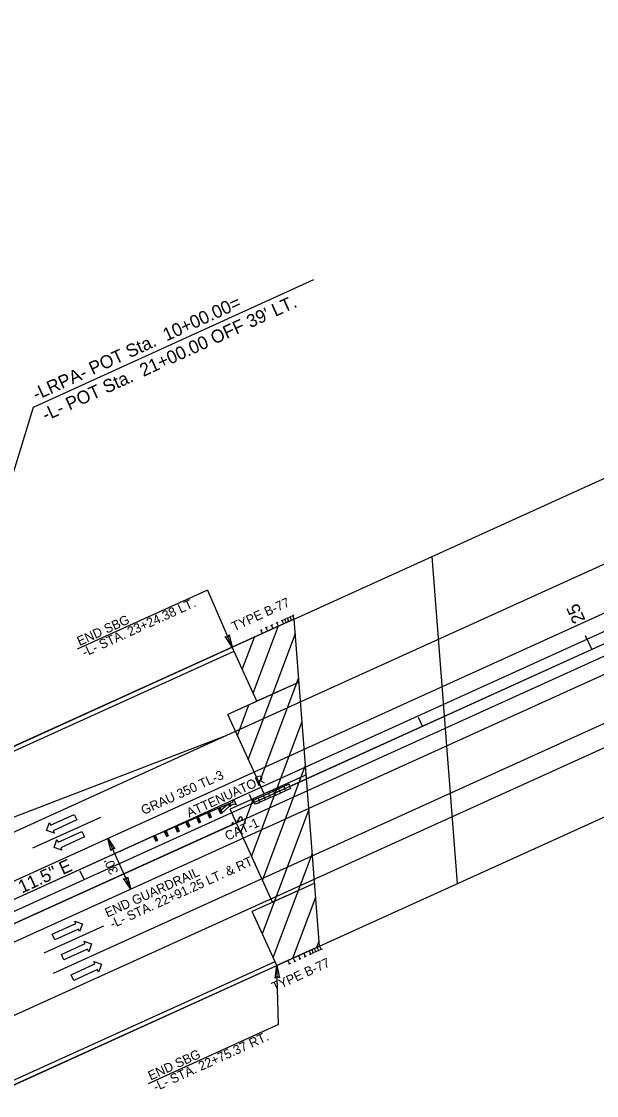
# Model space of a CAD drawing. Extents: x 2242984 to 2250974, y 661492 to 664681.
# Drawn here: x 2248742 to 2249051, y 663168 to 663746 of the extents above; entities that cross this region are included whole.
import ezdxf

# ---------------------------------------------------------------- set-up
doc = ezdxf.new("R2010")
doc.units = 0
for name, color, linetype in [('Prop Approach Slab', 7, 'Continuous'), ('Prop Approach Slab Hatching', 7, 'Continuous'), ('Prop Conc Barrier Precast Reinforced Single Face', 7, 'Continuous'), ('Prop Conc Shoulder Berm Gutter', 7, 'Continuous'), ('Prop Dimension', 7, 'Continuous'), ('Prop Dimension Text', 7, 'Continuous'), ('Prop DSN Text', 7, 'Continuous'), ('Prop EOT', 7, 'Continuous'), ('Prop Guardrail', 7, 'Continuous'), ('Prop Guardrail Anchor Unit CELL', 7, 'Continuous'), ('Prop Guardrail Attenuator CELL', 7, 'Continuous'), ('Prop Horizontal Alignment', 7, 'Continuous'), ('Prop Horizontal Alignment Direction Label', 7, 'Continuous'), ('Prop Horizontal Alignment Station Label', 7, 'Continuous'), ('Prop Horizontal Alignment Tick Label', 7, 'Continuous'), ('Prop Horizontal Alignment Tick Large', 7, 'Continuous'), ('Prop Horizontal Alignment Tick Small', 7, 'Continuous'), ('Prop Lane Arrow CELL', 7, 'Continuous'), ('Prop Lane Lines', 7, 'Continuous'), ('Prop Paved Shoulder', 7, 'Continuous'), ('Prop Roadway Bridge', 7, 'Continuous'), ('Prop Structure Anchor Unit CELL', 7, 'Continuous'), ('Prop Terminator CELL', 7, 'Continuous'), ('Scratch_Level_6', 7, 'Continuous'), ('Scratch_Level_8', 7, 'Continuous')]:
    doc.layers.add(name, color=color, linetype=linetype)

msp = doc.modelspace()

# ---------------------------------------------------------------- linework, layer by layer
at = {"layer": 'Prop Approach Slab'}
for p, q in [((2248888.56, 663424.38), (2248855.2, 663409.22)), ((2248868.43, 663380.09), (2248855.2, 663409.22)), ((2248891.19, 663390.43), (2248852.86, 663373.01)), ((2248891.19, 663390.43), (2248868.43, 663380.09)), ((2248875.62, 663383.35), (2248852.86, 663373.01)), ((2248872.3, 663330.22), (2248852.86, 663373.01)), ((2248895.06, 663340.56), (2248854.07, 663321.94)), ((2248895.06, 663340.56), (2248872.3, 663330.22)), ((2248876.82, 663271.87), (2248854.07, 663321.94)), ((2248899.58, 663282.21), (2248865.99, 663266.95)), ((2248899.58, 663282.21), (2248876.82, 663271.87)), ((2248879.23, 663237.81), (2248865.99, 663266.95)), ((2248902.21, 663248.25), (2248879.23, 663237.81))]:
    msp.add_line(p, q, dxfattribs=at)
at = {"layer": 'Prop Approach Slab Hatching'}
for p, q in [((2248866.47, 663384.41), (2248879.95, 663420.47)), ((2248860.61, 663397.31), (2248867.09, 663414.62)), ((2248863.84, 663348.84), (2248889.17, 663416.57)), ((2248869.7, 663335.95), (2248891, 663392.92)), ((2248857.98, 663361.73), (2248864.12, 663378.13)), ((2248865.62, 663296.51), (2248892.83, 663369.27)), ((2248871.48, 663283.61), (2248894.67, 663345.62)), ((2248859.77, 663309.4), (2248866.59, 663327.63)), ((2248871.44, 663254.95), (2248896.5, 663321.97)), ((2248877.3, 663242.06), (2248898.33, 663298.32)), ((2248887.85, 663241.73), (2248900.16, 663274.67)), ((2248900.71, 663247.57), (2248902, 663251.01))]:
    msp.add_line(p, q, dxfattribs=at)
at = {"layer": 'Prop Conc Barrier Precast Reinforced Single Face'}
msp.add_line((2248886.12, 663334.3), (2249152.79, 663455.44), dxfattribs=at)
at = {"layer": 'Prop Conc Shoulder Berm Gutter'}
for p, q in [((2248644.9, 663311.13), (2248856.16, 663407.1)), ((2248645.24, 663134.09), (2248878.26, 663239.94))]:
    msp.add_line(p, q, dxfattribs=at)
at = {"layer": 'Prop Dimension'}
msp.add_line((2248800.6, 663278.98), (2248788.19, 663306.3), dxfattribs=at)
at = {"layer": 'Prop DSN Text'}
for p, q in [((2248841.8, 663440.05), (2248771.74, 663408.13)), ((2248841.8, 663440.05), (2248855.2, 663409.22)), ((2248880.01, 663206), (2248879.23, 663237.81)), ((2248880.01, 663206), (2248809.95, 663174.07))]:
    msp.add_line(p, q, dxfattribs=at)
at = {"layer": 'Prop EOT'}
for p, q in [((2248850.37, 663360.9), (2249423.96, 663621.46)), ((2248200.21, 663039.2), (2249433.89, 663599.6)), ((2248212.61, 663011.89), (2249446.3, 663572.29)), ((2248401.88, 663058.32), (2249188.04, 663415.44)), ((2248850.37, 663360.9), (2248663.29, 663289.12))]:
    msp.add_line(p, q, dxfattribs=at)
at = {"layer": 'Prop Guardrail'}
for p, q in [((2248871.49, 663416.62), (2248643.94, 663313.26)), ((2248855.32, 663313.72), (2247994.71, 662922.79)), ((2248855.32, 663313.72), (2247994.71, 662922.79)), ((2247989.75, 662933.71), (2248810.53, 663306.55)), ((2247989.75, 662933.71), (2248810.53, 663306.55)), ((2248646.2, 663131.96), (2248885.14, 663240.5))]:
    msp.add_line(p, q, dxfattribs=at)
at = {"layer": 'Prop Guardrail Anchor Unit CELL'}
for p, q in [((2248855.39, 663325.82), (2248856.11, 663327.09)), ((2248855.39, 663325.82), (2248856.11, 663327.09)), ((2248856.11, 663327.09), (2248857.32, 663324.41)), ((2248856.11, 663327.09), (2248857.32, 663324.41)), ((2248810.53, 663306.55), (2248853.47, 663325.04)), ((2248810.53, 663306.55), (2248853.47, 663325.04)), ((2248847.59, 663322.5), (2248848.8, 663319.69)), ((2248847.59, 663322.5), (2248849.11, 663321.49)), ((2248847.59, 663322.5), (2248848.8, 663319.69)), ((2248847.59, 663322.5), (2248849.11, 663321.49)), ((2248848.2, 663321.1), (2248848.51, 663322.9)), ((2248848.2, 663321.1), (2248848.51, 663322.9)), ((2248848.2, 663321.1), (2248849.11, 663321.49)), ((2248848.2, 663321.1), (2248849.11, 663321.49)), ((2248849.72, 663320.09), (2248848.2, 663321.1)), ((2248849.72, 663320.09), (2248848.2, 663321.1)), ((2248848.51, 663322.9), (2248849.72, 663320.09)), ((2248848.51, 663322.9), (2248849.72, 663320.09)), ((2248849.11, 663321.49), (2248848.8, 663319.69)), ((2248849.11, 663321.49), (2248848.8, 663319.69)), ((2248849.11, 663321.49), (2248853.01, 663324.84)), ((2248849.11, 663321.49), (2248853.01, 663324.84)), ((2248849.72, 663320.09), (2248853.6, 663323.46)), ((2248849.72, 663320.09), (2248853.6, 663323.46)), ((2248853.01, 663324.84), (2248853.6, 663323.46)), ((2248854.52, 663323.85), (2248853.01, 663324.84)), ((2248853.01, 663324.84), (2248853.6, 663323.46)), ((2248854.52, 663323.85), (2248853.01, 663324.84)), ((2248853.53, 663324.98), (2248855.39, 663325.82)), ((2248853.53, 663324.98), (2248855.39, 663325.82)), ((2248853.78, 663324.42), (2248853.53, 663324.98)), ((2248853.78, 663324.42), (2248853.53, 663324.98)), ((2248853.93, 663325.23), (2248853.6, 663323.46)), ((2248853.93, 663325.23), (2248853.6, 663323.46)), ((2248853.6, 663323.46), (2248854.52, 663323.85)), ((2248853.6, 663323.46), (2248854.52, 663323.85)), ((2248853.6, 663323.46), (2248854.06, 663323.66)), ((2248853.6, 663323.46), (2248854.06, 663323.66)), ((2248854.03, 663323.86), (2248853.78, 663324.42)), ((2248854.03, 663323.86), (2248853.78, 663324.42)), ((2248853.93, 663325.23), (2248854.52, 663323.85)), ((2248853.93, 663325.23), (2248854.52, 663323.85)), ((2248855.9, 663324.71), (2248854.03, 663323.86)), ((2248855.9, 663324.71), (2248854.03, 663323.86)), ((2248857.32, 663324.41), (2248855.9, 663324.71)), ((2248857.32, 663324.41), (2248855.9, 663324.71)), ((2248830.23, 663315.03), (2248831.14, 663315.43)), ((2248830.23, 663315.03), (2248831.14, 663315.43)), ((2248830.23, 663315.03), (2248831.43, 663312.24)), ((2248830.23, 663315.03), (2248831.74, 663314.03)), ((2248830.23, 663315.03), (2248831.43, 663312.24)), ((2248830.23, 663315.03), (2248831.74, 663314.03)), ((2248830.83, 663313.64), (2248831.14, 663315.43)), ((2248830.83, 663313.64), (2248831.14, 663315.43)), ((2248831.14, 663315.43), (2248832.34, 663312.64)), ((2248831.14, 663315.43), (2248832.34, 663312.64)), ((2248836.01, 663317.52), (2248837.25, 663314.64)), ((2248836.01, 663317.52), (2248837.55, 663316.48)), ((2248836.01, 663317.52), (2248837.25, 663314.64)), ((2248836.01, 663317.52), (2248837.55, 663316.48)), ((2248836.63, 663316.08), (2248836.93, 663317.92)), ((2248836.63, 663316.08), (2248836.93, 663317.92)), ((2248836.63, 663316.08), (2248837.55, 663316.48)), ((2248836.63, 663316.08), (2248837.55, 663316.48)), ((2248838.17, 663315.04), (2248836.63, 663316.08)), ((2248838.17, 663315.04), (2248836.63, 663316.08)), ((2248836.93, 663317.92), (2248838.17, 663315.04)), ((2248836.93, 663317.92), (2248838.17, 663315.04)), ((2248837.55, 663316.48), (2248837.25, 663314.64)), ((2248837.55, 663316.48), (2248837.25, 663314.64)), ((2248837.25, 663314.64), (2248838.17, 663315.04)), ((2248837.25, 663314.64), (2248838.17, 663315.04)), ((2248841.8, 663320.01), (2248842.99, 663317.26)), ((2248841.8, 663320.01), (2248843.31, 663319.03)), ((2248841.8, 663320.01), (2248842.99, 663317.26)), ((2248841.8, 663320.01), (2248843.31, 663319.03)), ((2248842.39, 663318.64), (2248842.72, 663320.41)), ((2248842.39, 663318.64), (2248842.72, 663320.41)), ((2248842.39, 663318.64), (2248843.31, 663319.03)), ((2248842.39, 663318.64), (2248843.31, 663319.03)), ((2248843.91, 663317.65), (2248842.39, 663318.64)), ((2248843.91, 663317.65), (2248842.39, 663318.64)), ((2248842.72, 663320.41), (2248843.91, 663317.65)), ((2248842.72, 663320.41), (2248843.91, 663317.65)), ((2248843.31, 663319.03), (2248842.99, 663317.26)), ((2248843.31, 663319.03), (2248842.99, 663317.26)), ((2248842.99, 663317.26), (2248843.91, 663317.65)), ((2248842.99, 663317.26), (2248843.91, 663317.65)), ((2248848.8, 663319.69), (2248849.72, 663320.09)), ((2248848.8, 663319.69), (2248849.72, 663320.09)), ((2248855.63, 663314.75), (2248854.99, 663314.46)), ((2248855.32, 663313.72), (2248858.55, 663315.19)), ((2248855.32, 663313.72), (2248855.63, 663314.75)), ((2248855.96, 663314.01), (2248855.63, 663314.75)), ((2248858.3, 663315.52), (2248856.74, 663314.37)), ((2248858.46, 663316.03), (2248857.82, 663315.74)), ((2248857.82, 663315.74), (2248858.15, 663315.01)), ((2248858.79, 663315.3), (2248857.82, 663315.74)), ((2248858.15, 663315.01), (2248858.46, 663316.03)), ((2248858.15, 663315.01), (2248858.79, 663315.3)), ((2248858.79, 663315.3), (2248858.46, 663316.03)), ((2248858.73, 663317.01), (2248858.5, 663315.94)), ((2248858.55, 663315.19), (2248860.11, 663315.9)), ((2248858.67, 663315.24), (2248858.55, 663315.19)), ((2248818.65, 663310.05), (2248819.86, 663307.25)), ((2248818.65, 663310.05), (2248820.17, 663309.04)), ((2248818.65, 663310.05), (2248819.86, 663307.25)), ((2248818.65, 663310.05), (2248820.17, 663309.04)), ((2248819.25, 663308.65), (2248819.57, 663310.45)), ((2248819.25, 663308.65), (2248819.57, 663310.45)), ((2248819.25, 663308.65), (2248820.17, 663309.04)), ((2248819.25, 663308.65), (2248820.17, 663309.04)), ((2248819.57, 663310.45), (2248820.77, 663307.64)), ((2248819.57, 663310.45), (2248820.77, 663307.64)), ((2248820.17, 663309.04), (2248819.86, 663307.25)), ((2248820.17, 663309.04), (2248819.86, 663307.25)), ((2248824.44, 663312.54), (2248825.64, 663309.74)), ((2248824.44, 663312.54), (2248825.96, 663311.54)), ((2248824.44, 663312.54), (2248825.64, 663309.74)), ((2248824.44, 663312.54), (2248825.96, 663311.54)), ((2248825.04, 663311.14), (2248825.36, 663312.94)), ((2248825.04, 663311.14), (2248825.36, 663312.94)), ((2248825.04, 663311.14), (2248825.96, 663311.54)), ((2248825.04, 663311.14), (2248825.96, 663311.54)), ((2248826.56, 663310.14), (2248825.04, 663311.14)), ((2248826.56, 663310.14), (2248825.04, 663311.14)), ((2248825.36, 663312.94), (2248826.56, 663310.14)), ((2248825.36, 663312.94), (2248826.56, 663310.14)), ((2248825.96, 663311.54), (2248825.64, 663309.74)), ((2248825.96, 663311.54), (2248825.64, 663309.74)), ((2248825.64, 663309.74), (2248826.56, 663310.14)), ((2248825.64, 663309.74), (2248826.56, 663310.14)), ((2248830.83, 663313.64), (2248831.74, 663314.03)), ((2248830.83, 663313.64), (2248831.74, 663314.03)), ((2248832.34, 663312.64), (2248830.83, 663313.64)), ((2248832.34, 663312.64), (2248830.83, 663313.64)), ((2248831.74, 663314.03), (2248831.43, 663312.24)), ((2248831.74, 663314.03), (2248831.43, 663312.24)), ((2248831.43, 663312.24), (2248832.34, 663312.64)), ((2248831.43, 663312.24), (2248832.34, 663312.64)), ((2248854.99, 663314.46), (2248855.32, 663313.72)), ((2248855.96, 663314.01), (2248854.99, 663314.46)), ((2248855.32, 663313.72), (2248855.96, 663314.01)), ((2248812.86, 663307.56), (2248813.78, 663307.96)), ((2248812.86, 663307.56), (2248813.78, 663307.96)), ((2248812.86, 663307.56), (2248814.05, 663304.8)), ((2248814.37, 663306.58), (2248812.86, 663307.56)), ((2248812.86, 663307.56), (2248814.05, 663304.8)), ((2248814.37, 663306.58), (2248812.86, 663307.56)), ((2248813.45, 663306.18), (2248813.78, 663307.96)), ((2248813.45, 663306.18), (2248813.78, 663307.96)), ((2248813.45, 663306.18), (2248814.37, 663306.58)), ((2248813.45, 663306.18), (2248814.37, 663306.58)), ((2248814.97, 663305.2), (2248813.45, 663306.18)), ((2248814.97, 663305.2), (2248813.45, 663306.18)), ((2248813.78, 663307.96), (2248814.97, 663305.2)), ((2248813.78, 663307.96), (2248814.37, 663306.58)), ((2248813.78, 663307.96), (2248814.97, 663305.2)), ((2248813.78, 663307.96), (2248814.37, 663306.58)), ((2248814.37, 663306.58), (2248814.05, 663304.8)), ((2248814.37, 663306.58), (2248814.05, 663304.8)), ((2248814.05, 663304.8), (2248814.97, 663305.2)), ((2248814.05, 663304.8), (2248814.97, 663305.2)), ((2248820.77, 663307.64), (2248819.25, 663308.65)), ((2248820.77, 663307.64), (2248819.25, 663308.65)), ((2248819.86, 663307.25), (2248820.77, 663307.64)), ((2248819.86, 663307.25), (2248820.77, 663307.64))]:
    msp.add_line(p, q, dxfattribs=at)
msp.add_ellipse((2248859.7, 663316.8), major_axis=(-0.411, 0.904), ratio=0.995379, start_param=3.141593, end_param=7.214552, dxfattribs=at)
at = {"layer": 'Prop Guardrail Attenuator CELL'}
for p, q in [((2248880.14, 663332.96), (2248877.41, 663331.72)), ((2248882.87, 663334.2), (2248880.14, 663332.96)), ((2248880.14, 663332.96), (2248881.17, 663330.68)), ((2248885.6, 663335.44), (2248882.87, 663334.2)), ((2248882.87, 663334.2), (2248883.9, 663331.92)), ((2248886.63, 663333.16), (2248883.9, 663331.92)), ((2248885.6, 663335.44), (2248886.63, 663333.16)), ((2248868.3, 663327.58), (2248866.58, 663326.53)), ((2248866.58, 663326.53), (2248867, 663325.62)), ((2248869.21, 663328), (2248868.3, 663327.58)), ((2248871.94, 663329.24), (2248869.21, 663328)), ((2248869.21, 663328), (2248870.25, 663325.72)), ((2248872.98, 663326.96), (2248870.25, 663325.72)), ((2248874.68, 663330.48), (2248871.94, 663329.24)), ((2248871.94, 663329.24), (2248872.98, 663326.96)), ((2248875.71, 663328.2), (2248872.98, 663326.96)), ((2248877.41, 663331.72), (2248874.68, 663330.48)), ((2248874.68, 663330.48), (2248875.71, 663328.2)), ((2248878.44, 663329.44), (2248875.71, 663328.2)), ((2248877.41, 663331.72), (2248878.44, 663329.44)), ((2248881.17, 663330.68), (2248878.44, 663329.44)), ((2248883.9, 663331.92), (2248881.17, 663330.68)), ((2248867, 663325.62), (2248867.41, 663324.71)), ((2248869.34, 663325.31), (2248867.41, 663324.71)), ((2248870.25, 663325.72), (2248869.34, 663325.31))]:
    msp.add_line(p, q, dxfattribs=at)
at = {"layer": 'Prop Horizontal Alignment'}
msp.add_line((2247500.8, 662705.02), (2249793.08, 663746.29), dxfattribs=at)
at = {"layer": 'Prop Horizontal Alignment Station Label'}
for p, q in [((2248748.29, 663538.62), (2248899.07, 663607.33)), ((2248668.71, 663279.62), (2248748.29, 663538.62))]:
    msp.add_line(p, q, dxfattribs=at)
at = {"layer": 'Prop Horizontal Alignment Tick Large'}
msp.add_line((2249048.59, 663408.11), (2249045.28, 663415.39), dxfattribs=at)
at = {"layer": 'Prop Horizontal Alignment Tick Small'}
for p, q in [((2248957.54, 663366.75), (2248955.48, 663371.3)), ((2248866.5, 663325.39), (2248864.43, 663329.94)), ((2248775.45, 663284.03), (2248773.38, 663288.58))]:
    msp.add_line(p, q, dxfattribs=at)
at = {"layer": 'Prop Lane Arrow CELL'}
for p, q in [((2248755.33, 663310.51), (2248756.87, 663314.73)), ((2248756.87, 663314.73), (2248757.49, 663313.37)), ((2248757.49, 663313.37), (2248770.23, 663319.17)), ((2248771.6, 663316.17), (2248758.86, 663310.36)), ((2248770.23, 663319.17), (2248771.6, 663316.17)), ((2248759.48, 663309), (2248755.33, 663310.51)), ((2248758.86, 663310.36), (2248759.48, 663309)), ((2248761.51, 663304.22), (2248774.25, 663310.03)), ((2248774.25, 663310.03), (2248775.62, 663307.03)), ((2248759.35, 663301.37), (2248760.89, 663305.59)), ((2248760.89, 663305.59), (2248761.51, 663304.22)), ((2248775.62, 663307.03), (2248762.88, 663301.22)), ((2248763.5, 663299.85), (2248759.35, 663301.37)), ((2248762.88, 663301.22), (2248763.5, 663299.85)), ((2248758.3, 663254.59), (2248771.04, 663260.4)), ((2248772.41, 663257.39), (2248759.67, 663251.59)), ((2248771.04, 663260.4), (2248770.42, 663261.76)), ((2248770.42, 663261.76), (2248774.57, 663260.25)), ((2248773.03, 663256.03), (2248772.41, 663257.39)), ((2248774.57, 663260.25), (2248773.03, 663256.03)), ((2248759.67, 663251.59), (2248758.3, 663254.59)), ((2248763.28, 663243.78), (2248776.02, 663249.59)), ((2248777.39, 663246.58), (2248764.65, 663240.78)), ((2248776.02, 663249.59), (2248775.4, 663250.95)), ((2248775.4, 663250.95), (2248779.55, 663249.44)), ((2248778.01, 663245.22), (2248777.39, 663246.58)), ((2248779.55, 663249.44), (2248778.01, 663245.22)), ((2248764.65, 663240.78), (2248763.28, 663243.78)), ((2248781.28, 663238.6), (2248780.66, 663239.97)), ((2248780.66, 663239.97), (2248784.81, 663238.45)), ((2248768.54, 663232.8), (2248781.28, 663238.6)), ((2248782.65, 663235.6), (2248769.91, 663229.79)), ((2248783.27, 663234.23), (2248782.65, 663235.6)), ((2248784.81, 663238.45), (2248783.27, 663234.23)), ((2248769.91, 663229.79), (2248768.54, 663232.8))]:
    msp.add_line(p, q, dxfattribs=at)
at = {"layer": 'Prop Lane Lines'}
for p, q in [((2248759.04, 663233.74), (2249456.25, 663550.45)), ((2248668.27, 663278.18), (2248850.37, 663360.9)), ((2248747.92, 663301.18), (2248784.47, 663317.78)), ((2248754.08, 663244.65), (2248786.16, 663259.22))]:
    msp.add_line(p, q, dxfattribs=at)
at = {"layer": 'Prop Paved Shoulder'}
for p, q in [((2248894.79, 663344.83), (2249437.63, 663591.42)), ((2248895.78, 663332.1), (2249442.57, 663580.48)), ((2248638.25, 663310.67), (2248855.2, 663409.22)), ((2248203.91, 663031), (2248894.79, 663344.83)), ((2248208.89, 663020.08), (2248895.78, 663332.1)), ((2248646.2, 663131.96), (2248879.23, 663237.81))]:
    msp.add_line(p, q, dxfattribs=at)
at = {"layer": 'Prop Roadway Bridge'}
for p, q in [((2248888.56, 663424.38), (2249137.03, 663537.25)), ((2248976.37, 663281.94), (2248962.72, 663458.07)), ((2248902.21, 663248.25), (2248888.56, 663424.38)), ((2248902.21, 663248.25), (2249150.68, 663361.12))]:
    msp.add_line(p, q, dxfattribs=at)
at = {"layer": 'Prop Structure Anchor Unit CELL'}
for p, q in [((2248885.41, 663425.14), (2248884.37, 663424.67)), ((2248885.72, 663423.09), (2248884.89, 663424.91)), ((2248886.84, 663425.79), (2248885.79, 663425.32)), ((2248887.14, 663423.73), (2248886.31, 663425.55)), ((2248888.26, 663426.44), (2248887.22, 663425.96)), ((2248888.56, 663424.38), (2248887.74, 663426.2)), ((2248888.56, 663424.38), (2248871.49, 663416.62)), ((2248874.03, 663419.97), (2248872.99, 663419.5)), ((2248874.34, 663417.92), (2248873.51, 663419.74)), ((2248876.88, 663421.27), (2248875.83, 663420.79)), ((2248877.18, 663419.21), (2248876.36, 663421.03)), ((2248879.72, 663422.56), (2248878.68, 663422.09)), ((2248880.03, 663420.5), (2248879.2, 663422.32)), ((2248882.57, 663423.85), (2248881.53, 663423.38)), ((2248882.87, 663421.79), (2248882.05, 663423.62)), ((2248883.99, 663424.5), (2248882.95, 663424.02)), ((2248884.3, 663422.44), (2248883.47, 663424.26)), ((2248871.19, 663418.68), (2248870.14, 663418.21)), ((2248871.49, 663416.62), (2248870.67, 663418.45)), ((2248902.21, 663248.25), (2248885.14, 663240.5)), ((2248896.52, 663245.67), (2248897.35, 663243.85)), ((2248897.94, 663246.31), (2248898.77, 663244.49)), ((2248899.36, 663246.96), (2248900.19, 663245.14)), ((2248900.71, 663245.38), (2248899.67, 663244.9)), ((2248900.79, 663247.61), (2248901.61, 663245.79)), ((2248902.14, 663246.02), (2248901.09, 663245.55)), ((2248902.21, 663248.25), (2248903.04, 663246.43)), ((2248903.56, 663246.67), (2248902.52, 663246.2)), ((2248885.14, 663240.5), (2248885.97, 663238.68)), ((2248887.98, 663241.79), (2248888.81, 663239.97)), ((2248889.33, 663240.21), (2248888.29, 663239.73)), ((2248890.83, 663243.08), (2248891.66, 663241.26)), ((2248892.18, 663241.5), (2248891.13, 663241.03)), ((2248893.67, 663244.38), (2248894.5, 663242.56)), ((2248895.02, 663242.79), (2248893.98, 663242.32)), ((2248897.87, 663244.08), (2248896.83, 663243.61)), ((2248899.29, 663244.73), (2248898.25, 663244.26)), ((2248886.49, 663238.91), (2248885.44, 663238.44))]:
    msp.add_line(p, q, dxfattribs=at)
at = {"layer": 'Prop Terminator CELL'}
for points in [[(2248853.57, 663415.88), (2248855.2, 663409.22), (2248851.39, 663414.97), (2248852.84, 663414.66)], [(2248789.93, 663299.67), (2248788.19, 663306.3), (2248792.09, 663300.61), (2248790.65, 663300.9)], [(2248798.87, 663285.61), (2248800.6, 663278.98), (2248796.7, 663284.67), (2248798.15, 663284.38)], [(2248878.23, 663231.04), (2248879.23, 663237.81), (2248880.59, 663231.06), (2248879.37, 663231.89)]]:
    msp.add_lwpolyline(points, close=True, dxfattribs=at)
at = {"layer": 'Scratch_Level_6'}
for p, q in [((2248643.9, 663313.35), (2248888.59, 663424.5)), ((2248902.31, 663248.19), (2248646.24, 663131.87))]:
    msp.add_line(p, q, dxfattribs=at)
at = {"layer": 'Scratch_Level_8'}
for p, q in [((2248643.9, 663313.34), (2248866.79, 663414.59)), ((2248880.54, 663238.31), (2248646.24, 663131.88))]:
    msp.add_line(p, q, dxfattribs=at)

# ---------------------------------------------------------------- texts
at = {"layer": 'Prop Dimension Text'}
for s, rotation, p in [("30'", 114.43013, (2248794.06, 663288.23)), ('-L- STA. 22+91.25 LT. & RT.', 24.43013, (2248790.76, 663257.64)), ('END GUARDRAIL', 24.43013, (2248788.05, 663263.61))]:
    msp.add_text(s, height=5, rotation=rotation, dxfattribs=at).set_placement(p)
at = {"layer": 'Prop DSN Text'}
for s, p in [('-L- STA. 23+24.38 LT.', (2248775.79, 663403.91)), ('END SBG', (2248773.07, 663409.87)), ('-L- STA. 22+75.37 RT.', (2248814.01, 663169.85)), ('END SBG', (2248811.29, 663175.82))]:
    msp.add_text(s, height=5, rotation=24.49794, dxfattribs=at).set_placement(p)
at = {"layer": 'Prop Guardrail Anchor Unit CELL'}
for s, p in [('GRAU 350 TL-3', (2248807.48, 663318.83)), ('CAT-1', (2248852.61, 663304.9))]:
    msp.add_text(s, height=5, rotation=24.43013, dxfattribs=at).set_placement(p)
at = {"layer": 'Prop Guardrail Attenuator CELL'}
msp.add_text('ATTENUATOR', height=5, rotation=24.49794, dxfattribs=at).set_placement((2248831.99, 663317.45))
at = {"layer": 'Prop Horizontal Alignment Direction Label'}
msp.add_text('N 65%%d 34\' 11.5" E', height=7, rotation=24.43013, dxfattribs=at).set_placement((2248704.77, 663259.62))
at = {"layer": 'Prop Horizontal Alignment Station Label'}
for s, p in [('-LRPA- POT Sta.  10+00.00=', (2248749.77, 663542)), ("-L- POT Sta.  21+00.00 OFF 39' LT.", (2248754.84, 663530.87))]:
    msp.add_text(s, height=7, rotation=24.49794, dxfattribs=at).set_placement(p)
at = {"layer": 'Prop Horizontal Alignment Tick Label'}
msp.add_text('25', height=7, rotation=114.43013, dxfattribs=at).set_placement((2249045.35, 663423.94))
at = {"layer": 'Prop Structure Anchor Unit CELL'}
for p in [(2248856.24, 663417.76), (2248877.82, 663223.68)]:
    msp.add_text('TYPE B-77', height=5, rotation=24.49794, dxfattribs=at).set_placement(p)

doc.saveas('drawing.dxf')
